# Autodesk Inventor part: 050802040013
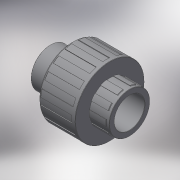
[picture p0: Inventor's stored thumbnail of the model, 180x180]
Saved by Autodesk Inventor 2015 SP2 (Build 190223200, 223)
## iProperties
Created: 2017-10
Part Number: 050802040013
Material: Generic
Description: PLASSON UNION+O RING THR-CEM 40-1.1/4"
Document SubType Name: Modeling
Designer: KIM
Density: 1 g/cm^3
Appearance: Default
Author: KIM
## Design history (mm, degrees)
derived "050802.ipt"
feature "Solid1::050802.ipt"
tag "TaggingFeature1"
body "Solid1"
other parameters: "d0" = 66, "d4" = 38.952, "d5" = 48, "d7" = 51.2, "d8" = 72, "d9" = 26, "d10" = 24, "d11" = 34, "d12" = 38, "d14" = 18, "d15" = 19.5, "d16" = 14.4, "d17" = 2.4, "d19" = 70.56, "d20" = 2.6, "d21" = 2.16, "d25" = 7.2, "d26" = 3.6, "d27" = 23.31, "d28" = 0, "d32" = 7.2, "d33" = 3.6, "d35" = 0, "d39" = 0.4, "d45" = 0.6, "d49" = 360 deg, "d51" = 0.72, "d55" = 360 deg, "E_" = 72, "H_" = 39, "l_" = 26, "lt_" = 24, "Z_" = 11, "G_" = 38.952, "d13" = 16, "d24" = 25.9, "d40" = 0.6, "d44" = 0.72
